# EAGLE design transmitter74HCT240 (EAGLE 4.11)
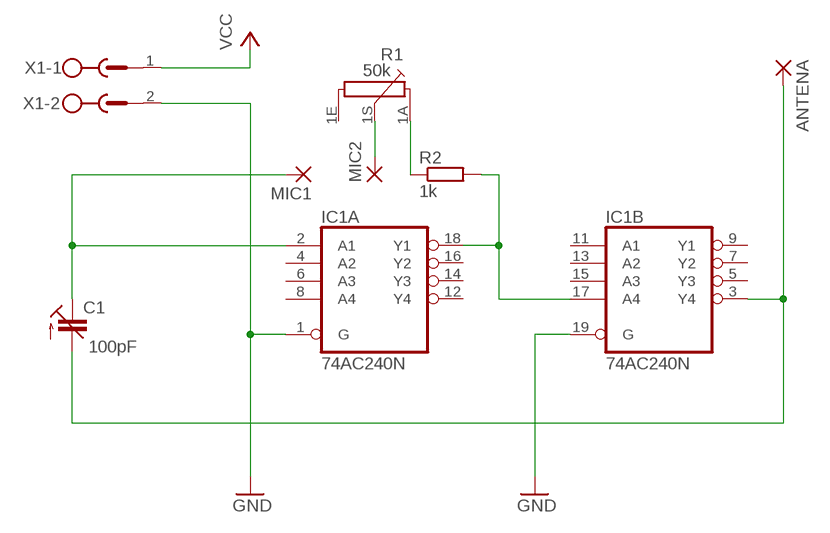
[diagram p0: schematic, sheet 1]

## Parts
ANTENA  3,17/1,3  [3,17/1,3]
C1  100pF  C-TRIMM808-7.5  [CTRIM808-BC7.5]
IC1  74AC240N  [DIL20]
MIC1  3,17/1,1  [3,17/1,1]
MIC2  3,17/1,1  [3,17/1,1]
R1  50k  PC16S  [PC16S]
R2  1k  R-EU_0204/7  [0204/7]
X1  MSTBV2  [MSTBV2]

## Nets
GND: IC1.1(A:G) IC1.19(B:G) X1.2
N$1: IC1.17(B:A4) IC1.18(A:Y1) R2.2
N$2: ANTENA.1(P) C1.2(A) IC1.3(B:Y4)
N$3: C1.1(E) IC1.2(A:A1) MIC1.1(P)
N$4: MIC2.1(P) R1.1S
N$5: R1.1A R2.1
VCC: X1.1
Unconnected: IC1.4(A:A2) IC1.5(B:Y3) IC1.6(A:A3) IC1.7(B:Y2) IC1.8(A:A4) IC1.9(B:Y1) IC1.11(B:A1) IC1.12(A:Y4) IC1.13(B:A2) IC1.14(A:Y3) IC1.15(B:A3) IC1.16(A:Y2) R1.1E

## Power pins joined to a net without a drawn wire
GND: IC1.10(P:GND)
VCC: IC1.20(P:VCC)

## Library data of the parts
ANTENA = wirepad:3,17/1,3: THROUGH-HOLE PAD
C1 = rcl:C-TRIMM: Trimm capacitor
IC1 = 74xx-eu:74*240: Octal BUFFER and LINE DRIVER, 3-state
MIC1 MIC2 = wirepad:3,17/1,1: THROUGH-HOLE PAD
R1 = piher:PC16S: POTENTIOMETER single carbon potentiometer, 16 mm, S3ROH
R2 = rcl:R-EU_: RESISTOR, European symbol
X1 = con-phoenix-500:MSTBV2: PHOENIX

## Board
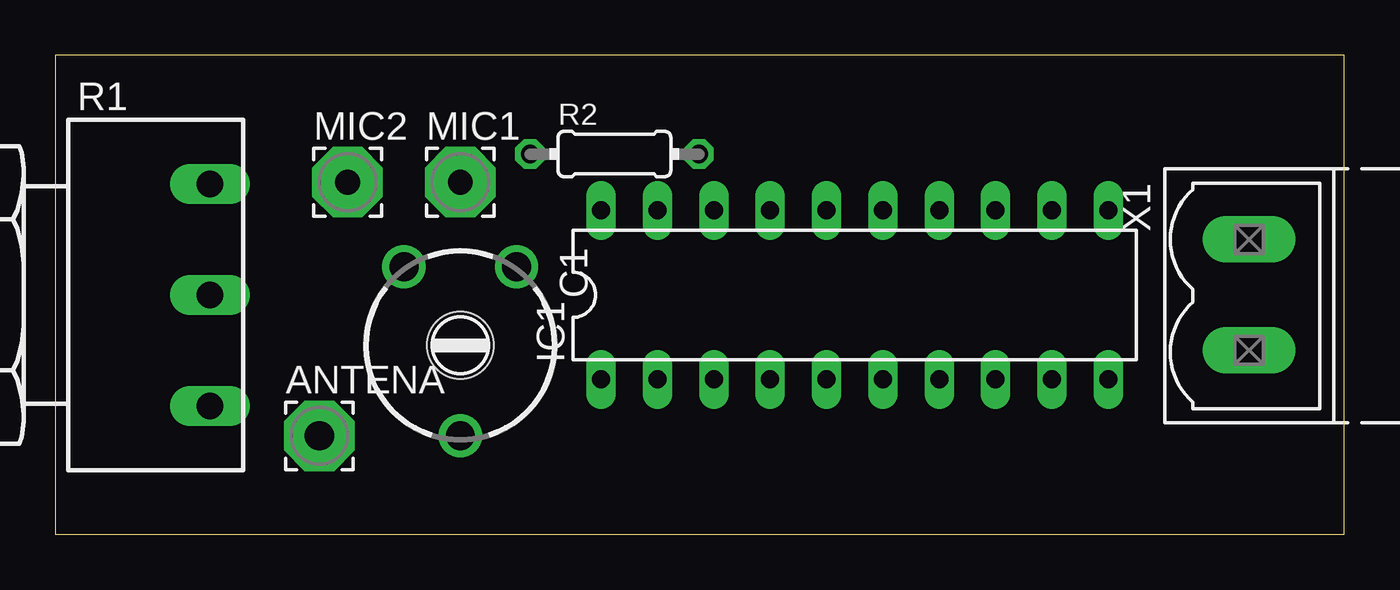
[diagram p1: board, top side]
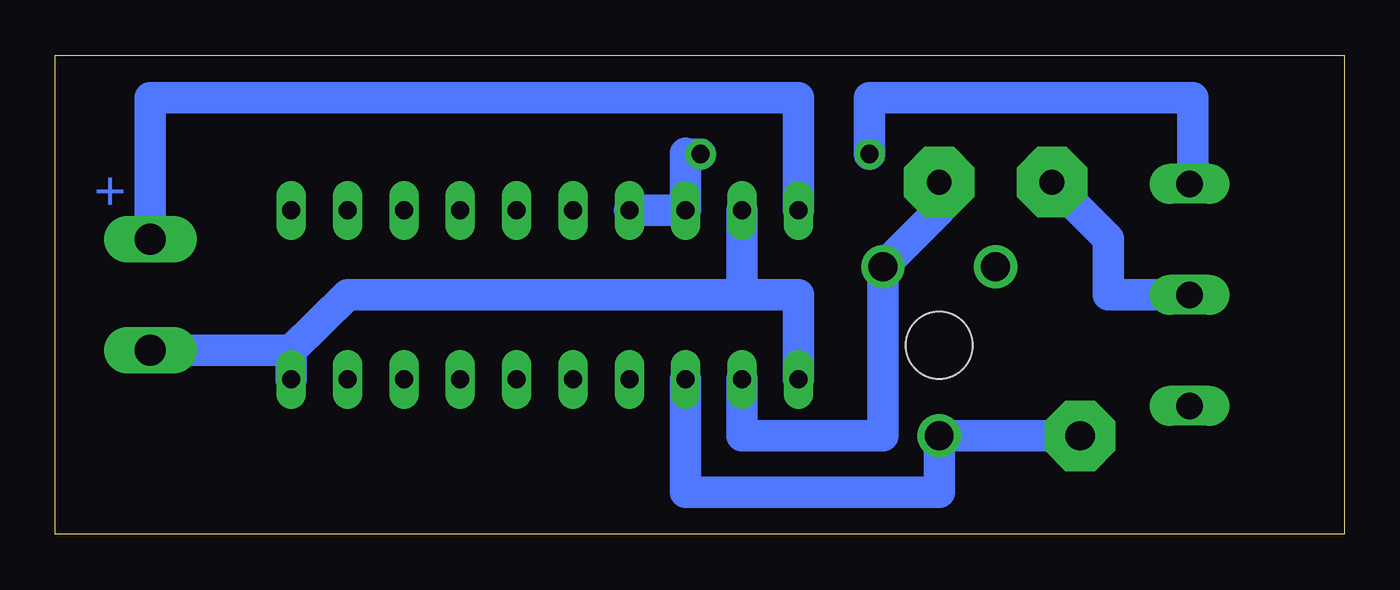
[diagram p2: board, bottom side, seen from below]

Size 58.09 x 21.58 mm. Coordinates in mm from the lower left corner, seen from the top.
Outline: 0,0 58.09,0 58.09,21.58 0,21.58 0,0
Copper layers (1*16): Top 0.035mm / dielectric 1.5mm / Bottom 0.035mm
Design rules "default": minimum track width 10mil, minimum drill 24mil, track to track 8mil, track to pad 8mil, pad to pad 8mil, via to via 8mil, smd to smd 8mil, copper to edge 40mil, drill to drill 8mil, minimum pad ring 10mil, minimum via ring 8mil, stop-mask expansion 4mil, vias tented up to drill 0mil, thermal gap 10mil

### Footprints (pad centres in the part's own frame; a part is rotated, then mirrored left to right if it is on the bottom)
3,17/1,3 = drill 1.321 pad 3.175 octagon: 1 0,0
CTRIM808-BC7.5 = drill 1.3 round: 1 -2.54,-2.54; 2 0,5.08; 3 2.54,-2.54 | hole 3: 0,1
DIL20 = drill 0.813 long: 1 -11.43,-3.81; 2 -8.89,-3.81; 3 -6.35,-3.81; 4 -3.81,-3.81; 5 -1.27,-3.81; 6 1.27,-3.81; 7 3.81,-3.81; 8 6.35,-3.81; 9 8.89,-3.81; 10 11.43,-3.81; 11 11.43,3.81; 12 8.89,3.81; 13 6.35,3.81; 14 3.81,3.81; 15 1.27,3.81; 16 -1.27,3.81; 17 -3.81,3.81; 18 -6.35,3.81; 19 -8.89,3.81; 20 -11.43,3.81
3,17/1,1 = drill 1.118 pad 3.175 octagon: 1 0,0
PC16S = drill 1.2 long: 1A -5,6.5; 1E 5,6.5; 1S 0,6.5
0204/7 = drill 0.813 octagon: 1 -3.81,0; 2 3.81,0
MSTBV2 = drill 1.397 long: 1 -2.5,0; 2 2.5,0

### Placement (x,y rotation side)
ANTENA  11.9,4.44 0 top
C1  18.25,9.52 180 top
IC1  36.03,10.79 0 top
MIC1  18.25,15.87 0 top
MIC2  13.17,15.87 0 top
R1  0.47,10.79 270 top
R2  25.2,17.14 0 top
X1  53.81,10.79 270 top

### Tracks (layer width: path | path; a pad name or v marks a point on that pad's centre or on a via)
GND
  Bottom 1.422: 47.46,8.29 X1.2 | 47.46,8.29 IC1.10 | IC1.1 24.6,10.79 27.14,10.79 | 27.14,10.79 IC1.19 | 47.46,8.29 44.92,10.79 27.14,10.79
N$1
  Bottom 1.422: IC1.17 IC1.18 29.68,17.18 29.68,17.14 R2.2
N$2
  Bottom 1.422: ANTENA.1 C1.2 18.25,1.9 29.68,1.9 IC1.3
N$3
  Bottom 1.422: IC1.2 27.14,4.44 20.79,4.44 C1.1 18.25,14.6 MIC1.1
N$4
  Bottom 1.422: R1.1S 10.63,10.79 10.63,13.33 MIC2.1
N$5
  Bottom 1.422: R1.1A 6.82,15.79 6.82,19.68 21.39,19.68 R2.1
VCC
  Bottom 1.422: IC1.20 24.6,19.68 53.81,19.68 X1.1

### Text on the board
Bottom: +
